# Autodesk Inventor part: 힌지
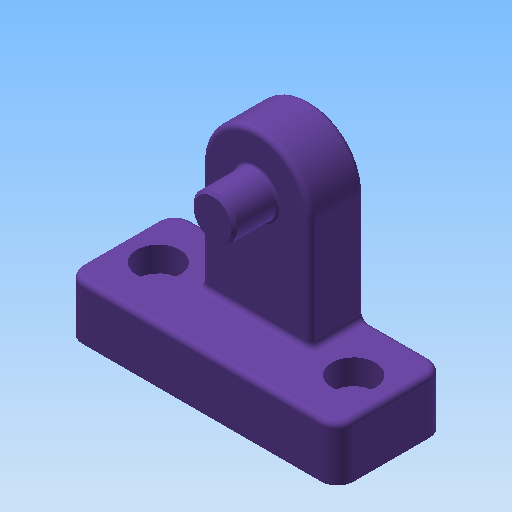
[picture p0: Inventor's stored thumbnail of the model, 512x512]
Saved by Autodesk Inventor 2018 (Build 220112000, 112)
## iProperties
Created: 2017-07
Part Number: 힌지
Material: 알루미늄 6061
Document SubType Name: Modeling
Designer: mduedu
Density: 2.71 g/cm^3
Mass: 41.2292 g
Surface Area: 53.4313 cm^2
Volume: 15.2137 cm^3
Appearance: 보라색
Author: mduedu
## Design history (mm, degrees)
sketch "스케치1"
  geometry: L1 (-25, 0)-(25, 0); L2 (-25, 10)-(25, 10); L3 (-25, 0)-(-25, 10); L4 (25, 0)-(25, 10); L5 (-10, 10)-(10, 10); L6 (10, 10)-(10, 40); L7 (10, 40)-(-10, 40); L8 (-10, 40)-(-10, 10); 3 further points
  constraints: 16 end point, 4 parallel, 2 horizontal, 2 midpoint, 2 perpendicular, 1 coincident, 1 point on line, 1 vertical alignment
  dimensions: "d0" = 50 distance of L1.start L1.end; "d2" = 10 distance of L1.end L2.end; "d3" = 20 distance of L6.end L7.end; "d4" = 40 distance between parallel lines of L7 L1
extrude "돌출1" new body sketch "스케치1" stored distance "d5" = 20; taper "d6" = 0 deg
extrude "돌출2" join sketch "스케치1" distance "d7" = 10; taper "d8" = 0 deg
fillet "모깎기1"
sketch "스케치2"
  geometry: C1 r 4 at (0, 30); A1 r 10 centre (0, 30) between (10, 30) and (-10, 30) reference; 1 further point
  constraints: 1 centre point, 1 coincident
  dimensions: "d9" = 8 diameter of C1
extrude "돌출3" join sketch "스케치2" distance "d10" = 8; taper "d11" = 0 deg
fillet "모깎기2" dims "d12" = 0.5
fillet "모깎기3" dims "d13" = 1
fillet "모깎기4" dims "d14" = 1
fillet "모깎기5" dims "d15" = 3
fillet "모깎기6" dims "d16" = 1
chamfer "모따기1" distance "d18" = 0.5; stored, may be unused: second distance "d19" = 2, angle "d20" = 45 deg
sketch "스케치3"
  geometry: L1 (-16, 8)-(-16, -6) reference; L2 (34, -6)-(34, 8) reference; L3 (-16, 1)-(34, 1); L4 (-13, -9)-(31, -9) reference; L5 (9, 1)-(9, -9); 2 further points
  constraints: 4 end point, 3 midpoint, 1 point on line, 1 symmetric about line
  dimensions: "d21" = 7 distance from line of point (-9, 1) L1
sketch "스케치4"
  geometry: L1 (-16, 1)-(34, 1) reference; L2 (9, 1)-(9, -9) reference; 7 further points
  constraints: 2 coincident
hole "구멍1" sketch "스케치4" at (27, 1), (-9, 1) diameter "d22" = 4.5; stored, may be unused: countersink angle "d26" = 90 deg, drill point angle "d28" = 0 deg; dims "d23" = 6, "d24" = 8, "d25" = 4.6, "d27" = 8
node "솔리드1"
